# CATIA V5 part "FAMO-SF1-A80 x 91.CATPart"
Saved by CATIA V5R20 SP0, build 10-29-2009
Part number: FAMO-SF1-A80 x 91
Definition: NONE
Nomenclature: FAMO-SF1-A80 x 91
Source: Unknown
Description: FAMO-SF1-A80 x 91
Bounding box of the stored display mesh (mm): x -13 to 78, y -55.5 to 55.5, z -55.5 to 55.5
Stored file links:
  C:\Users\Utente\Desktop\IO LAVORO\3D X SITO CF\X SITO\FAMO\FAMO-SF1-A80 x 91.CATPart
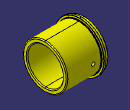
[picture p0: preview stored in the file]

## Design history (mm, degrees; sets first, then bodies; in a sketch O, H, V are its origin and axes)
Body1 "FAMO-SF1-A80 x 91" (main body)
  Solid1: solid without history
